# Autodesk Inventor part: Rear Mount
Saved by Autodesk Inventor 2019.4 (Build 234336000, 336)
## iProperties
Created: 2020-09
Part Number: Rear Mount
Material: Generic
Document SubType Name: Modeling
Designer: Administrator
Density: 1 g/cm^3
Appearance: Default
Title: Rear Mount
Author: Administrator
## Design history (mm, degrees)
feature "Body1"
body "Solid1"
